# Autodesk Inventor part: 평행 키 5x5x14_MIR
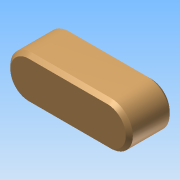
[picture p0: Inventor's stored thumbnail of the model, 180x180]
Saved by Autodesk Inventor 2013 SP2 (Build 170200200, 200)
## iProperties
Created: 2026-07
Part Number: 평행 키 5x5x14_MIR
Material: Generic
Document SubType Name: Modeling
Designer: aa
Density: 1 g/cm^3
Author: aa
변환 표준: STEP AP214IS
전처리기: Build: 200, Release: 2013 SP2 Update 6 - Date: Thu 07/17/2014
전송 단위: 밀리미터
불확실성: 0.01
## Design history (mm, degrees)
derived "평행 키 5x5x14.ipt"
feature "솔리드1::평행 키 5x5x14.ipt" dims "d0" = 10
tag "피쳐 태그1"
node "솔리드1"
